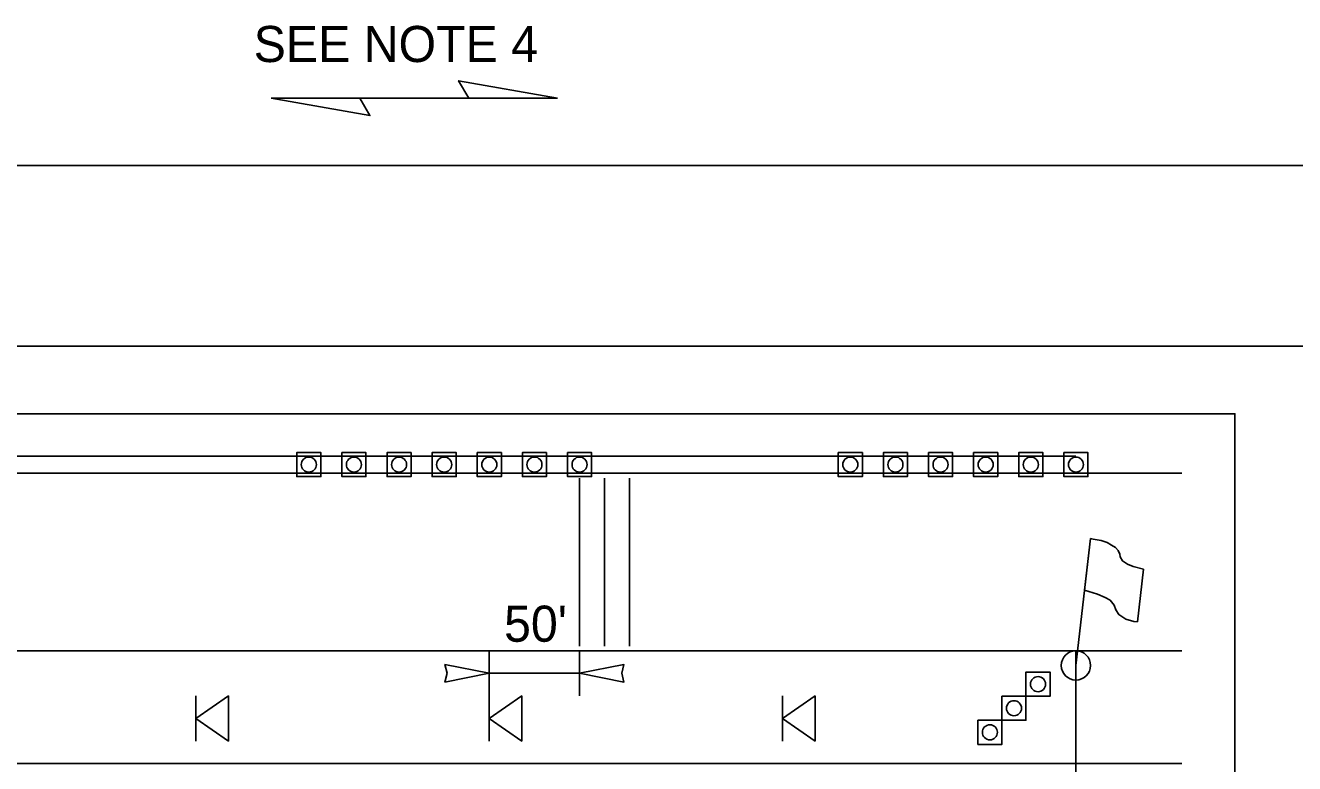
# Model space of a CAD drawing. Extents: x 99999.1 to 100095.7, y 99995 to 100010.7.
# Drawn here: x 100006.43 to 100009.243, y 100004.807 to 100006.443 of the extents above; entities that cross this region are included whole.
import ezdxf

# ---------------------------------------------------------------- set-up
doc = ezdxf.new("R2010")
doc.units = 0
for name, color, linetype in [('RD_ED_ShoulderPavedEdge', 7, 'Continuous'), ('RD_MK_LineDblYellowCenter', 7, 'Continuous'), ('RD_MK_LineEdgeWhite', 7, 'Continuous'), ('RD_MK_LineNoPass', 7, 'Continuous'), ('RD_MK_LineSkipCenter', 7, 'Continuous'), ('TR_WZ_FlaggingStation', 7, 'Continuous'), ('TR_WZ_PortableSignMountBlk-Org', 7, 'Continuous'), ('TR_WZ_TrafficCone', 7, 'Continuous'), ('TR_WZ_WorkZoneDetails', 7, 'Continuous'), ('TR_WZ_WorkZoneTextCurrent', 7, 'Continuous')]:
    doc.layers.add(name, color=color, linetype=linetype)

msp = doc.modelspace()

# ---------------------------------------------------------------- linework, layer by layer
at = {"layer": 'RD_ED_ShoulderPavedEdge'}
for p, q in [((100000.1076, 100005.7323), (100015.6424, 100005.7323)), ((100005.2015, 100004.8073), (100008.9925, 100004.8073))]:
    msp.add_line(p, q, dxfattribs=at)
at = {"layer": 'RD_MK_LineDblYellowCenter'}
for p, q in [((100005.2015, 100005.4886), (100008.0081, 100005.4886)), ((100005.2015, 100005.4511), (100008.0081, 100005.4511))]:
    msp.add_line(p, q, dxfattribs=at)
at = {"layer": 'RD_MK_LineEdgeWhite'}
for p, q in [((100000.1076, 100006.1323), (100015.6424, 100006.1323)), ((100005.2015, 100005.0573), (100008.9925, 100005.0573))]:
    msp.add_line(p, q, dxfattribs=at)
at = {"layer": 'RD_MK_LineNoPass'}
msp.add_line((100008.0081, 100005.4886), (100008.7581, 100005.4886), dxfattribs=at)
at = {"layer": 'RD_MK_LineSkipCenter'}
msp.add_lwpolyline([(100008.9925, 100005.4511), (100008.0081, 100005.4511)], dxfattribs=at)
at = {"layer": 'TR_WZ_FlaggingStation'}
for p, q in [((100008.7581, 100005.0248), (100008.7901, 100005.3058)), ((100008.7771, 100005.1917), (100008.7902, 100005.3061)), ((100008.9081, 100005.2383), (100008.8948, 100005.1211)), ((100008.7771, 100005.1917), (100008.7771, 100005.1917))]:
    msp.add_line(p, q, dxfattribs=at)
for points in [[(100008.7902, 100005.3061), (100008.7959, 100005.3048), (100008.8137, 100005.3014), (100008.8276, 100005.2972), (100008.8372, 100005.2911), (100008.8458, 100005.2864), (100008.8515, 100005.2796), (100008.8557, 100005.2717), (100008.8562, 100005.2655), (100008.8616, 100005.2563), (100008.8724, 100005.2489), (100008.8848, 100005.2437), (100008.9081, 100005.2383)], [(100008.8948, 100005.1211), (100008.8867, 100005.1225), (100008.869, 100005.1271), (100008.8533, 100005.1376), (100008.8468, 100005.1482), (100008.8429, 100005.1585), (100008.8338, 100005.1694), (100008.8229, 100005.1756), (100008.8055, 100005.1827), (100008.7771, 100005.1917)]]:
    msp.add_lwpolyline(points, dxfattribs=at)
msp.add_circle((100008.7581, 100005.0248), 0.0325, dxfattribs=at)
at = {"layer": 'TR_WZ_PortableSignMountBlk-Org'}
for p, q in [((100006.8081, 100004.8574), (100006.8081, 100004.9574)), ((100007.4581, 100004.8574), (100007.4581, 100004.9574)), ((100008.1081, 100004.8574), (100008.1081, 100004.9574))]:
    msp.add_line(p, q, dxfattribs=at)
for points in [[(100006.8081, 100004.9073), (100006.8799, 100004.9574), (100006.8799, 100004.8574)], [(100007.4581, 100004.9073), (100007.5299, 100004.9574), (100007.5299, 100004.8574)], [(100008.1081, 100004.9073), (100008.1799, 100004.9574), (100008.1799, 100004.8574)]]:
    msp.add_lwpolyline(points, close=True, dxfattribs=at)
at = {"layer": 'TR_WZ_TrafficCone'}
for points in [[(100007.0848, 100005.4965), (100007.0314, 100005.4965), (100007.0314, 100005.4432), (100007.0848, 100005.4432), (100007.0848, 100005.4965)], [(100007.0848, 100005.4432), (100007.0314, 100005.4432), (100007.0314, 100005.4965), (100007.0848, 100005.4965), (100007.0848, 100005.4432)], [(100007.1848, 100005.4965), (100007.1314, 100005.4965), (100007.1314, 100005.4432), (100007.1848, 100005.4432), (100007.1848, 100005.4965)], [(100007.1848, 100005.4432), (100007.1314, 100005.4432), (100007.1314, 100005.4965), (100007.1848, 100005.4965), (100007.1848, 100005.4432)], [(100007.2848, 100005.4965), (100007.2314, 100005.4965), (100007.2314, 100005.4432), (100007.2848, 100005.4432), (100007.2848, 100005.4965)], [(100007.2848, 100005.4432), (100007.2314, 100005.4432), (100007.2314, 100005.4965), (100007.2848, 100005.4965), (100007.2848, 100005.4432)], [(100007.3848, 100005.4965), (100007.3314, 100005.4965), (100007.3314, 100005.4432), (100007.3848, 100005.4432), (100007.3848, 100005.4965)], [(100007.3848, 100005.4432), (100007.3314, 100005.4432), (100007.3314, 100005.4965), (100007.3848, 100005.4965), (100007.3848, 100005.4432)], [(100007.4848, 100005.4965), (100007.4314, 100005.4965), (100007.4314, 100005.4432), (100007.4848, 100005.4432), (100007.4848, 100005.4965)], [(100007.4848, 100005.4432), (100007.4314, 100005.4432), (100007.4314, 100005.4965), (100007.4848, 100005.4965), (100007.4848, 100005.4432)], [(100007.5848, 100005.4965), (100007.5314, 100005.4965), (100007.5314, 100005.4432), (100007.5848, 100005.4432), (100007.5848, 100005.4965)], [(100007.5848, 100005.4432), (100007.5314, 100005.4432), (100007.5314, 100005.4965), (100007.5848, 100005.4965), (100007.5848, 100005.4432)], [(100007.6848, 100005.4965), (100007.6314, 100005.4965), (100007.6314, 100005.4432), (100007.6848, 100005.4432), (100007.6848, 100005.4965)], [(100007.6848, 100005.4432), (100007.6314, 100005.4432), (100007.6314, 100005.4965), (100007.6848, 100005.4965), (100007.6848, 100005.4432)], [(100008.2848, 100005.4965), (100008.2314, 100005.4965), (100008.2314, 100005.4432), (100008.2848, 100005.4432), (100008.2848, 100005.4965)], [(100008.2848, 100005.4432), (100008.2314, 100005.4432), (100008.2314, 100005.4965), (100008.2848, 100005.4965), (100008.2848, 100005.4432)], [(100008.3848, 100005.4965), (100008.3314, 100005.4965), (100008.3314, 100005.4432), (100008.3848, 100005.4432), (100008.3848, 100005.4965)], [(100008.3848, 100005.4432), (100008.3314, 100005.4432), (100008.3314, 100005.4965), (100008.3848, 100005.4965), (100008.3848, 100005.4432)], [(100008.4848, 100005.4965), (100008.4314, 100005.4965), (100008.4314, 100005.4432), (100008.4848, 100005.4432), (100008.4848, 100005.4965)], [(100008.4848, 100005.4432), (100008.4314, 100005.4432), (100008.4314, 100005.4965), (100008.4848, 100005.4965), (100008.4848, 100005.4432)], [(100008.5848, 100005.4965), (100008.5314, 100005.4965), (100008.5314, 100005.4432), (100008.5848, 100005.4432), (100008.5848, 100005.4965)], [(100008.5848, 100005.4432), (100008.5314, 100005.4432), (100008.5314, 100005.4965), (100008.5848, 100005.4965), (100008.5848, 100005.4432)], [(100008.6848, 100005.4965), (100008.6314, 100005.4965), (100008.6314, 100005.4432), (100008.6848, 100005.4432), (100008.6848, 100005.4965)], [(100008.6848, 100005.4432), (100008.6314, 100005.4432), (100008.6314, 100005.4965), (100008.6848, 100005.4965), (100008.6848, 100005.4432)], [(100008.7848, 100005.4965), (100008.7314, 100005.4965), (100008.7314, 100005.4432), (100008.7848, 100005.4432), (100008.7848, 100005.4965)], [(100008.7848, 100005.4432), (100008.7314, 100005.4432), (100008.7314, 100005.4965), (100008.7848, 100005.4965), (100008.7848, 100005.4432)], [(100008.6474, 100005.01), (100008.7008, 100005.01), (100008.7008, 100004.9567), (100008.6474, 100004.9567), (100008.6474, 100005.01)], [(100008.6474, 100004.9567), (100008.7008, 100004.9567), (100008.7008, 100005.01), (100008.6474, 100005.01), (100008.6474, 100004.9567)], [(100008.5941, 100004.9567), (100008.6474, 100004.9567), (100008.6474, 100004.9033), (100008.5941, 100004.9033), (100008.5941, 100004.9567)], [(100008.5941, 100004.9033), (100008.6474, 100004.9033), (100008.6474, 100004.9567), (100008.5941, 100004.9567), (100008.5941, 100004.9033)], [(100008.5408, 100004.9033), (100008.5941, 100004.9033), (100008.5941, 100004.85), (100008.5408, 100004.85), (100008.5408, 100004.9033)], [(100008.5408, 100004.85), (100008.5941, 100004.85), (100008.5941, 100004.9033), (100008.5408, 100004.9033), (100008.5408, 100004.85)]]:
    msp.add_lwpolyline(points, dxfattribs=at)
for centre in [(100007.0581, 100005.4698), (100007.1581, 100005.4698), (100007.2581, 100005.4698), (100007.3581, 100005.4698), (100007.4581, 100005.4698), (100007.5581, 100005.4698), (100007.6581, 100005.4698), (100008.2581, 100005.4698), (100008.3581, 100005.4698), (100008.4581, 100005.4698), (100008.5581, 100005.4698), (100008.6581, 100005.4698), (100008.7581, 100005.4698), (100008.6741, 100004.9833), (100008.6208, 100004.93), (100008.5674, 100004.8767)]:
    msp.add_circle(centre, 0.0167, dxfattribs=at)
at = {"layer": 'TR_WZ_WorkZoneDetails'}
for p, q in [((100007.1713, 100006.2816), (100007.4124, 100006.2816)), ((100007.4124, 100006.2816), (100007.1713, 100006.2816)), ((100007.6581, 100005.0673), (100007.6581, 100005.4398)), ((100007.7137, 100005.0673), (100007.7137, 100005.4398)), ((100007.7686, 100005.0673), (100007.7686, 100005.4398)), ((100007.4581, 100004.9574), (100007.4581, 100005.0573)), ((100007.6581, 100005.0573), (100007.6581, 100004.9574)), ((100008.7581, 100005.0573), (100008.7581, 100004.5823)), ((100007.6581, 100005.0074), (100007.4581, 100005.0074))]:
    msp.add_line(p, q, dxfattribs=at)
for points in [[(100007.609, 100006.2816), (100007.3901, 100006.3202), (100007.4124, 100006.2816)], [(100006.9748, 100006.2816), (100007.1936, 100006.243), (100007.1713, 100006.2816)], [(100007.4581, 100005.0074), (100007.3598, 100004.9881), (100007.3644, 100005.0074), (100007.3598, 100005.0267)], [(100007.6581, 100005.0074), (100007.7564, 100004.9881), (100007.7518, 100005.0074), (100007.7564, 100005.0267)]]:
    msp.add_lwpolyline(points, close=True, dxfattribs=at)
at = {"layer": 'TR_WZ_WorkZoneTextCurrent'}
msp.add_lwpolyline([(100005.1015, 100005.5823), (100009.1102, 100005.5823), (100009.1102, 100003.4799), (100005.1015, 100003.4799)], close=True, dxfattribs=at)

# ---------------------------------------------------------------- texts
for s, p in [('SEE NOTE 4', (100006.9359, 100006.3616)), ("50'", (100007.4908, 100005.0773))]:
    msp.add_text(s, height=0.08, dxfattribs=at).set_placement(p)

doc.saveas('drawing.dxf')
